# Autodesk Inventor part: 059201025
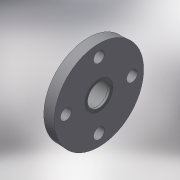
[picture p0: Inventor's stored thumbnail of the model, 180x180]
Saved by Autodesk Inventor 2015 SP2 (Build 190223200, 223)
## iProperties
Created: 2017-10
Part Number: 059201025
Material: Generic
Description: PLASSON THR. FIXED FLANGE PVC 2.1/2"
Document SubType Name: Modeling
Designer: KIM
Density: 1 g/cm^3
Appearance: Default
Author: KIM
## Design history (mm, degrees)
derived "059201.ipt"
feature "Solid1::059201.ipt"
tag "TaggingFeature1"
body "Solid1"
other parameters: "d0" = 47, "d2" = 185, "d3" = 183.15, "d14" = 18, "d15" = 72.5, "d16" = 47, "d17" = 0, "d19" = 360 deg, "d21" = 29, "d22" = 72.226, "d23" = 68.6147, "d25" = 0.72226, "d26" = 0.925, "d27" = 0.925, "d28" = 0.925, "d29" = 0.925, "d30" = 0.925, "d31" = 0.925, "d32" = 0.37, "d33" = 0, "d34" = 19, "d35" = 86.6712, "E_" = 185, "H_" = 47, "Dp_" = 145, "S_" = 18, "lt_" = 29, "G_" = 72.226, "H_1" = 19
